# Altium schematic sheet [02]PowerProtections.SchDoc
size A4; SheetNumber: 2; SheetTotal: 5
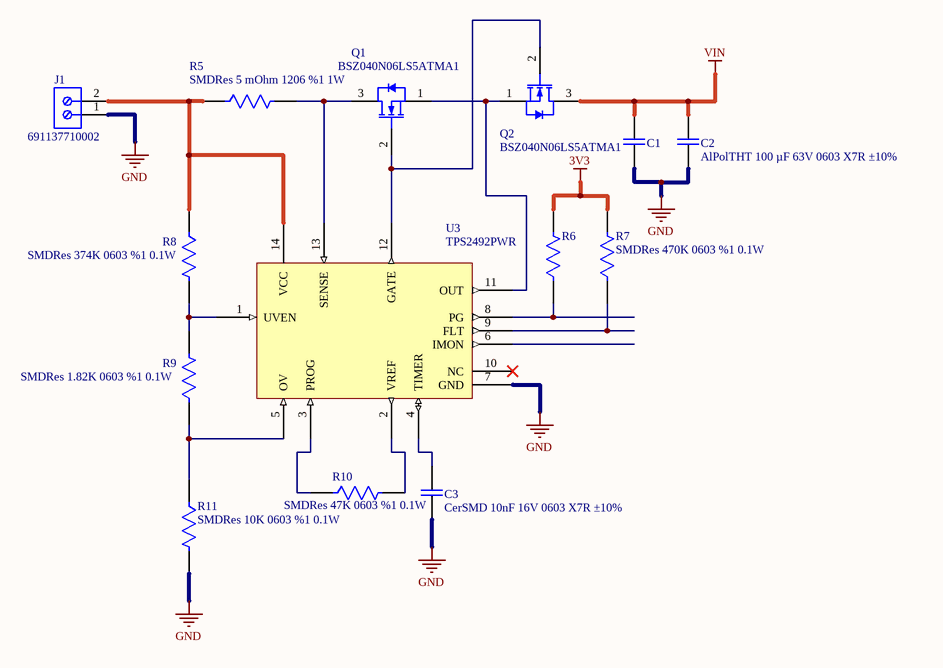
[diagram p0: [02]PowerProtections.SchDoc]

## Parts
C1  AlPolTHT 100 µF 63V 0603 X7R ±10%  [107AVG063MFBJ]  (value not drawn)
C2  AlPolTHT 100 µF 63V 0603 X7R ±10%  [107AVG063MFBJ]
C3  CerSMD 10nF 16V 0603 X7R ±10%  [CAPC1608X09N]
J1  691137710002  [691137710002]
Q1  BSZ040N06LS5ATMA1  [PG-TSDSON-8-FL]
Q2  BSZ040N06LS5ATMA1  [PG-TSDSON-8-FL]
R5  SMDRes 5 mOhm 1206 %1 1W  [RESC3116X10N]
R6  SMDRes 470K 0603 %1 0.1W  [RESC1508X06N]  (value not drawn)
R7  SMDRes 470K 0603 %1 0.1W  [RESC1508X06N]
R8  SMDRes 374K 0603 %1 0.1W  [RESC1508X06N]
R9  SMDRes 1.82K 0603 %1 0.1W  [RESC1508X06N]
R10  SMDRes 47K 0603 %1 0.1W  [RESC1508X06N]
R11  SMDRes 10K 0603 %1 0.1W  [RESC1508X06N]
U3  TPS2492PWR  [TSOP65P640X120-14L]

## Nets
3V3: R6.2 R7.2
GND: C1.2 C2.2 C3.2 J1.1 R11.2 U3.7(GND)
VIN: C1.1 C2.1 Q2.3(D)
NetC3_1: C3.1 U3.4(TIMER)
NetJ1_2: J1.2 R5.1 R8.1 U3.14(VCC)
NetQ1_1: Q1.1(S) Q2.1(S) U3.11(OUT)
NetQ1_2: Q1.2(G) Q2.2(G) U3.12(GATE)
NetQ1_3: Q1.3(D) R5.2 U3.13(SENSE)
NetR6_1: R6.1 U3.8(PG)
NetR7_1: R7.1 U3.9(FLT)
NetR8_2: R8.2 R9.2 U3.1(UVEN)
NetR9_1: R9.1 R11.1 U3.5(OV)
NetR10_1: R10.1 U3.3(PROG)
NetR10_2: R10.2 U3.2(VREF)

Not connected (* = marked no-connect by the designer): U3 6(IMON) 10(NC)*

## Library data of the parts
C1 C2 = CMP-00002-4: Ceramic Capacitor SMD 100 µF 63V 0603 X7R ±10%; Manufacturer: Cornell Dubilier Knowles
C3 = CMP-00001-3: Ceramic Capacitor SMD  10nF 16V 0603 X7R ±10%; Manufacturer Number: CL10B103KO8WPNC; Manufacturer: Samsung Electro-Mechanics
J1 = CMP-00022-1: würth terminal
Q1 Q2 = CMP-00004-1: N-MOS 60V 17A (Ta) 101A (Tc)
R5 = CMP-00007-2: 5 mOhms ±1% 1W Chip Resistor 1206 (3216 Metric) Automotive AEC-Q200, Current Sense, Moisture Resistant Metal Foil; Manufacturer Number: CSRF1206FT5L00; Manufacturer: Stackpole Electronics Inc
R6 R7 = CMP-00006-1: Res Thick Film 0603 470K Ohm 1% 0.1W(1/10W) ±100ppm/C Pad SMD T/R Automotive AEC-Q200; Manufacturer: Stackpole Electronics Inc; Manufacturer Number: RMCF0603FT470K
R8 = CMP-00005-2: Res Thick Film 0603 374K Ohm 1% 0.1W(1/10W) ±100ppm/C Pad SMD T/R Automotive AEC-Q200; Manufacturer: Stackpole Electronics Inc; Manufacturer Number: RMCF0603FT374K
R9 = CMP-00003-2: Res Thick Film 0603 1.82K Ohm 1% 0.1W(1/10W) ±100ppm/C Pad SMD T/R Automotive AEC-Q200; Manufacturer: Stackpole Electronics Inc; Manufacturer Number: RMCF0603FT1K82
R10 = CMP-00008-1: Res Thick Film 0603 47K Ohm 1% 0.1W(1/10W) ±100ppm/C Pad SMD T/R Automotive AEC-Q200; Manufacturer Number: RMCF0603FT47K0; Manufacturer: Stackpole Electronics Inc
R11 = CMP-00001-1-1: Res Thick Film 0603 10K Ohm 1% 0.1W(1/10W) ±100ppm/C Pad SMD T/R Automotive AEC-Q200; Manufacturer Number: RMCF0603FT10K0; Manufacturer: Stackpole Electronics Inc
U3 = CMP-00000-1: eFuses - External MOSFETs - 9V-80V; Manufacturer: Texas Instruments; Temperature Rating: -40°C up to 125°C; Voltage Rating: 9V up to 80V; Internal Switch(s): No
